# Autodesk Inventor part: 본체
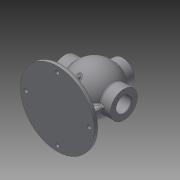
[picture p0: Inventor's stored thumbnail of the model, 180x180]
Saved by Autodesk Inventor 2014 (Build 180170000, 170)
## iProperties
Created: 2020-08
Part Number: 본체
Material: Generic
Document SubType Name: Modeling
Designer: kh
Density: 1 g/cm^3
Appearance: Default
Author: kh
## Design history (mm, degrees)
sketch "Sketch1"
  geometry: C1 r 85 at (0, 0); 1 further point
  constraints: 1 centre point, 1 coincident
  dimensions: "d0" = 170 diameter of C1
extrude "Extrusion1" new body sketch "Sketch1" distance "d1" = 10; taper "d2" = 0 deg
sketch "Sketch2"
  geometry: L1 (-53, 85)-(53, 85); A1 r 53 centre (0, 85) between (-53, 85) and (53, 85); 3 further points
  constraints: 2 coincident, 2 end point, 2 point on circle, 1 centre point, 1 horizontal, 1 midpoint, 1 vertical alignment
  dimensions: "d4" = 85 distance of point (0, 0) point (0, 85); "d5" = 106 diameter of A1
revolve "Revolution1" sketch "Sketch2" stored, may be unused: angle "d6" = 90 deg
sketch "Sketch3"
  geometry: L1 (-68, 85)-(68, 85); L2 (-85, 0)-(85, 0) reference; L3 (-68, 85)-(-68, 116); L4 (-68, 116)-(68, 116); L5 (68, 116)-(68, 85); 3 further points
  constraints: 8 end point, 2 midpoint, 2 perpendicular, 1 horizontal, 1 parallel, 1 vertical alignment
  dimensions: "d7" = 85 distance between parallel lines of L2 L1; "d8" = 136 distance of L1.start L1.end; "d9" = 62 diameter of L4 L1
revolve "Revolution2" sketch "Sketch3" stored, may be unused: angle "d10" = 90 deg
workplane "Work Plane1"
sketch "Sketch4"
  geometry: C1 r 27 at (0, 0); 1 further point
  constraints: 1 centre point, 1 coincident
  dimensions: "d12" = 54 diameter of C1
extrude "Extrusion2" join sketch "Sketch4" stored distance "d13" = 10; taper "d14" = 0 deg
sketch "Sketch5"
  geometry: L1 (-43, 85)-(43, 85); A1 r 53 centre (0, 85) between (42.988, 116) and (42.988, 54) reference; A2 r 43 centre (0, 85) between (-43, 85) and (43, 85); 2 further points
  constraints: 2 coincident, 2 end point, 2 point on circle, 1 centre point, 1 horizontal, 1 midpoint
  dimensions: "d15" = 86 diameter of A2
revolve "Revolution3" sketch "Sketch5" stored, may be unused: angle "d16" = 90 deg
sketch "Sketch6"
  geometry: L1 (-68, 85)-(68, 85); L2 (-68, 54)-(-68, 116) reference; L3 (68, 54)-(68, 116) reference; L4 (-68, 85)-(-68, 102.5); L5 (68, 102.5)-(68, 85); L6 (-68, 102.5)-(-52, 102.5); L7 (-52, 102.5)-(-52, 103.5); L8 (-52, 103.5)-(-50.25, 103.5); L9 (-50.25, 103.5)-(-50.25, 102.5); L10 (-50.25, 102.5)-(68, 102.5); 1 further point
  constraints: 16 end point, 3 parallel, 3 perpendicular, 2 midpoint, 2 point on line, 1 collinear, 1 horizontal
  dimensions: "d17" = 85 distance from line of point (0, 0) L1; "d19" = 37 diameter of L8 L1; "d20" = 35 diameter of L10 L1; "d21" = 1.75 distance between parallel lines of L9 L7; "d22" = 16 distance from line of L6.end L2
revolve "Revolution4" sketch "Sketch6" stored, may be unused: angle "d23" = 90 deg
hole "Hole1" diameter "d26" = 26; stored, may be unused: countersink angle "d30" = 90 deg, drill point angle "d32" = 118 deg; dims "d24" = 10, "d25" = 10, "d27" = 6, "d28" = 4, "d29" = 2, "d31" = 8
chamfer "Chamfer1" distance "d33" = 1; stored, may be unused: second distance "d34" = 2, angle "d35" = 45 deg
workplane "Work Plane2"
sketch "Sketch7"
  geometry: L1 (-38.739, -5.998)-(38.739, -5.998); L2 (38.739, -5.998)-(38.739, -12.002); L3 (38.739, -12.002)-(-38.739, -12.002); L4 (-38.739, -12.002)-(-38.739, -5.998); L5 (-27, 0)-(-27, -19.393) reference; L6 (0, -12.002)-(0, -5.998); L7 (-27, 0)-(27, 0) reference; L8 (-38.739, -9)-(38.739, -9); 1 further point
  constraints: 4 end point, 4 midpoint, 2 other
  dimensions: "d37" = 9 distance between parallel lines of L7 L8; "d38" = 27 distance between parallel lines of L5 L6
emboss "Emboss1" sketch "Sketch7" dims "d39" = 0.5, "d40" = 0
sketch "Sketch8"
  geometry: L1 (52, -4)-(52, 4); L2 (-52, 4)-(-52, -4); L3 (-52, -4)-(52, 4); L4 (52, -4)-(-52, 4); L5 (-4, -43)-(4, -43); L6 (4, 43)-(-4, 43); L7 (-4, -43)-(4, 43); L8 (4, -43)-(-4, 43); L9 (-4, 4)-(-52, 4); L10 (-4, 43)-(-4, 4); L11 (52, 4)-(4, 4); L12 (-4, -4)-(-4, -43); L13 (4, -43)-(4, -4); L14 (4, 4)-(4, 43); L15 (-52, -4)-(-4, -4); L16 (4, -4)-(52, -4); 1 further point
  constraints: 32 end point, 10 parallel, 4 collinear, 4 midpoint, 4 perpendicular, 3 horizontal
  dimensions: "d41" = 104 distance of L2.start L1.end; "d42" = 86 distance between parallel lines of L5 L6; "d45" = 8 distance between parallel lines of L13 L12; "d46" = 8 distance between parallel lines of L11 L16
extrude "Extrusion3" join sketch "Sketch8" stored distance "d47" = 10; taper "d48" = 0 deg
sketch "Sketch9" dims "d49" = 48
  geometry: L1 (0, 0)-(0, 24); C1 r 31 at (0, 0) reference; 2 further points
  constraints: 2 coincident, 2 end point, 1 vertical, 1 vertical alignment, 2 other
hole "Hole2" sketch "Sketch9" at (0, 24) diameter "d50" = 3.242; stored, may be unused: countersink angle "d54" = 90 deg, drill point angle "d56" = 118 deg; dims "d51" = 12, "d52" = 4, "d53" = 2, "d55" = 15
pattern_circular "Circular Pattern1" dims angle "d58" = 360 deg
mirror "Mirror1"
sketch "Sketch10" dims "d60" = 40
  geometry: L1 (0, 0)-(0, 20); 2 further points
  constraints: 2 coincident, 2 end point, 1 vertical, 1 vertical alignment, 2 other
hole "Hole3" sketch "Sketch10" at (0, 20) diameter "d61" = 3.242; stored, may be unused: countersink angle "d65" = 90 deg, drill point angle "d67" = 118 deg; dims "d62" = 12, "d63" = 4, "d64" = 2, "d66" = 15
pattern_circular "Circular Pattern2" dims angle "d69" = 360 deg
sketch "Sketch11" dims "d71" = 145
  geometry: L1 (0, 0)-(0, 72.5); 3 further points
  constraints: 3 coincident, 2 end point, 1 vertical, 1 vertical alignment, 2 other
hole "Hole4" sketch "Sketch11" at (0, 72.5) diameter "d72" = 9; stored, may be unused: countersink angle "d76" = 90 deg, drill point angle "d78" = 118 deg; dims "d73" = 12, "d74" = 4, "d75" = 2, "d77" = 15
pattern_circular "Circular Pattern3" dims angle "d80" = 360 deg
fillet "Fillet1" dims "d82" = 3
fillet "Fillet2" dims "d83" = 3
body "Solid1"
other parameters: "d43" = 8, "d44" = 8
